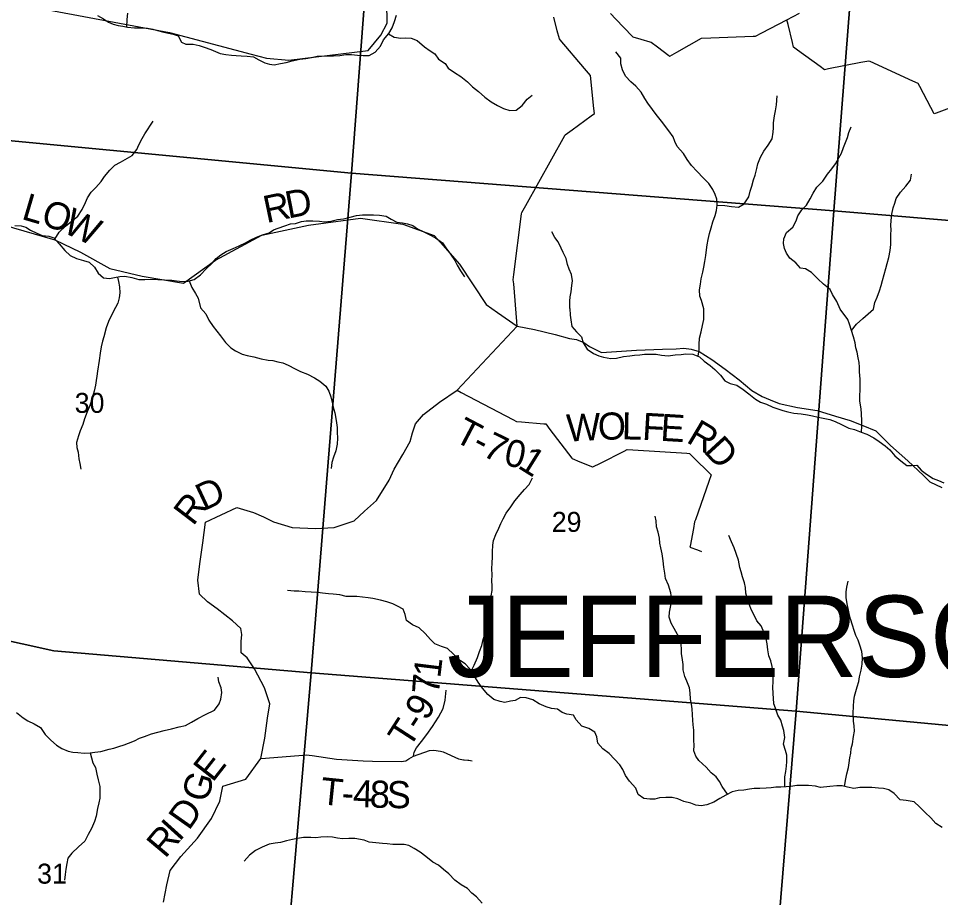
# Model space of a CAD drawing. Extents: x 1715311 to 2083412, y 146837 to 553079.
# Drawn here: x 1917955 to 1928164, y 312214 to 321945 of the extents above; entities that cross this region are included whole.
import ezdxf

# ---------------------------------------------------------------- set-up
doc = ezdxf.new("R2010")
doc.units = 0
for name, color, linetype in [('GM_X_County_Road', 7, 'Continuous'), ('GM_X_County_Road_Text', 7, 'Continuous'), ('GM_X_Minor_River', 7, 'Continuous'), ('GM_X_Section', 7, 'Continuous'), ('GM_X_Section_Text', 7, 'Continuous'), ('GM_X_State_Route', 7, 'Continuous'), ('GM_X_Township_Road', 7, 'Continuous'), ('GM_X_Township_Road_Text', 7, 'Continuous'), ('GM_X_Township_Text', 7, 'Continuous')]:
    doc.layers.add(name, color=color, linetype=linetype)

msp = doc.modelspace()

# ---------------------------------------------------------------- linework, layer by layer
at = {"layer": 'GM_X_County_Road'}
for points in [[(1924510, 321999), (1924569, 321937), (1924749, 321749), (1924758, 321740), (1924846, 321716), (1924946, 321688), (1924961, 321684), (1925032, 321631), (1925156, 321536), (1925167, 321528), (1925246, 321572), (1925518, 321725), (1925519, 321726), (1925622, 321730), (1926091, 321749), (1926117, 321750), (1926186, 321786), (1926463, 321930), (1926602, 322003)], [(1923476, 318540), (1923472, 318592), (1923438, 319007), (1923434, 319052), (1923441, 319111), (1923526, 319782), (1923528, 319797), (1923572, 319875), (1924003, 320649), (1924008, 320657), (1924084, 320713), (1924295, 320866), (1924334, 320894), (1924327, 320950), (1924288, 321312), (1924288, 321315), (1924222, 321392), (1923952, 321710), (1923944, 321720), (1923921, 321808), (1923883, 321960)], [(1916337, 320578), (1916337, 320577), (1916816, 320281), (1917394, 319907), (1917761, 319670), (1917901, 319629), (1918358, 319494), (1918643, 319358), (1918967, 319178), (1919324, 319092), (1919781, 319014), (1920137, 319268), (1920649, 319545), (1921165, 319656), (1921742, 319733), (1922209, 319667), (1922557, 319541), (1922629, 319465), (1922838, 319226), (1923134, 318780), (1923259, 318692), (1923476, 318540)], [(1919562, 312162), (1919597, 312354), (1919634, 312514), (1919751, 312668), (1919936, 312873), (1920092, 313088), (1920183, 313280), (1920216, 313446), (1920472, 313524), (1920639, 313753), (1920683, 313977), (1920713, 314199), (1920740, 314357), (1920679, 314536), (1920569, 314747), (1920486, 314868), (1920422, 314922), (1920421, 315048), (1920428, 315126), (1920418, 315191), (1920325, 315279), (1920156, 315409), (1920047, 315487), (1919961, 315574), (1919940, 315726), (1919962, 315908), (1919995, 316140), (1920027, 316369), (1920374, 316531), (1920557, 316477), (1920667, 316429), (1920778, 316374), (1920984, 316312), (1921243, 316299), (1921451, 316309), (1921673, 316384), (1921788, 316491), (1921921, 316609), (1922060, 316834), (1922113, 316956), (1922212, 317118), (1922293, 317261), (1922318, 317357), (1922352, 317459), (1922439, 317561), (1922618, 317696), (1922814, 317829), (1923476, 318540)], [(1923476, 318540), (1923667, 318502), (1923897, 318447), (1924055, 318403), (1924133, 318393), (1924213, 318359), (1924277, 318313), (1924411, 318249), (1924797, 318275), (1925085, 318286), (1925237, 318288), (1925323, 318296), (1925403, 318286), (1925493, 318258), (1925633, 318170), (1925779, 318064), (1925935, 317945), (1926074, 317825), (1926190, 317761), (1926276, 317723), (1926376, 317682), (1926582, 317638), (1926798, 317606), (1927002, 317544), (1927162, 317496), (1927302, 317439), (1927446, 317379), (1927610, 317217), (1927802, 317048), (1927977, 316886), (1928047, 316816), (1928177, 316754)]]:
    msp.add_lwpolyline(points, dxfattribs=at)
at = {"layer": 'GM_X_Minor_River'}
for points in [[(1919155, 321850), (1919160, 321932), (1919167, 322005)], [(1918829, 321976), (1918897, 321941), (1918952, 321905), (1919004, 321883), (1919058, 321867), (1919110, 321859), (1919164, 321848), (1919240, 321842), (1919314, 321840), (1919384, 321838), (1919443, 321827), (1919495, 321811), (1919563, 321795), (1919617, 321783), (1919669, 321770), (1919723, 321752), (1919759, 321684), (1919810, 321662), (1919888, 321662), (1919956, 321647), (1920010, 321627), (1920084, 321603), (1920136, 321579), (1920188, 321558), (1920251, 321546), (1920315, 321538), (1920367, 321534), (1920419, 321531), (1920489, 321529), (1920557, 321519), (1920615, 321487), (1920682, 321452), (1920736, 321438), (1920788, 321432), (1920856, 321446), (1920918, 321458), (1920984, 321475)], [(1920984, 321475), (1921070, 321495), (1921138, 321503), (1921200, 321513), (1921264, 321526), (1921368, 321530), (1921444, 321532), (1921514, 321535), (1921580, 321545), (1921644, 321547), (1921710, 321539), (1921771, 321536), (1921837, 321534), (1921905, 321570), (1921962, 321638), (1921996, 321710), (1922054, 321779), (1922092, 321843), (1922120, 321913), (1922141, 321981)], [(1922051, 321776), (1922114, 321739), (1922188, 321727), (1922244, 321731), (1922303, 321728), (1922371, 321700), (1922451, 321630), (1922515, 321586), (1922566, 321553), (1922606, 321493), (1922678, 321447), (1922712, 321395), (1922781, 321346), (1922853, 321302), (1922925, 321244), (1922983, 321189), (1923048, 321137), (1923120, 321075), (1923188, 321023), (1923257, 320980), (1923325, 320948), (1923395, 320926), (1923467, 320931), (1923531, 320983), (1923589, 321051), (1923641, 321097)], [(1925544, 318731), (1925517, 318822), (1925499, 318872), (1925497, 318940), (1925505, 319002), (1925515, 319062), (1925532, 319136), (1925544, 319192), (1925554, 319254), (1925566, 319322), (1925573, 319382), (1925581, 319440), (1925591, 319500), (1925605, 319564), (1925623, 319626), (1925644, 319694), (1925670, 319764), (1925684, 319818), (1925692, 319880), (1925689, 319944), (1925667, 319998), (1925643, 320052), (1925599, 320117), (1925536, 320179), (1925470, 320251), (1925408, 320316), (1925359, 320384), (1925317, 320452), (1925247, 320526), (1925221, 320582), (1925202, 320635), (1925156, 320701), (1925076, 320809), (1925015, 320883), (1924975, 320936), (1924925, 321006), (1924890, 321060), (1924848, 321130), (1924790, 321195), (1924735, 321245), (1924677, 321307), (1924643, 321375), (1924625, 321443), (1924626, 321507), (1924570, 321576)], [(1925692, 319880), (1925776, 319874), (1925848, 319862), (1925926, 319855), (1925988, 319893), (1926040, 319969), (1926058, 320035), (1926075, 320087), (1926093, 320157), (1926111, 320209), (1926131, 320283), (1926141, 320335), (1926170, 320409), (1926208, 320477), (1926256, 320544), (1926298, 320614), (1926312, 320686), (1926313, 320736), (1926315, 320788), (1926327, 320868), (1926337, 320922), (1926346, 320990), (1926354, 321090)], [(1918357, 319503), (1918407, 319580), (1918475, 319645), (1918535, 319695), (1918613, 319757), (1918661, 319831), (1918697, 319909), (1918720, 319961), (1918760, 320023), (1918812, 320072), (1918870, 320140), (1918908, 320194), (1918966, 320266), (1919022, 320320), (1919085, 320356), (1919161, 320397), (1919215, 320427), (1919267, 320493), (1919287, 320545), (1919325, 320617), (1919355, 320669), (1919448, 320809)], [(1927054, 318728), (1927017, 318812), (1926969, 318889), (1926943, 318945), (1926868, 319005), (1926804, 319061), (1926736, 319134), (1926668, 319174), (1926614, 319182), (1926563, 319240), (1926497, 319293), (1926459, 319347), (1926436, 319397), (1926424, 319455), (1926428, 319505), (1926460, 319575), (1926528, 319633), (1926566, 319703), (1926585, 319759), (1926627, 319827), (1926679, 319878), (1926719, 319948), (1926753, 320010), (1926796, 320076), (1926860, 320144), (1926914, 320220), (1926962, 320280), (1927002, 320335), (1927038, 320401), (1927069, 320455), (1927091, 320515), (1927111, 320573), (1927133, 320629), (1927149, 320681), (1927176, 320747)], [(1927420, 318727), (1927438, 318801), (1927462, 318861), (1927488, 318929), (1927507, 318989), (1927523, 319043), (1927539, 319111), (1927557, 319177), (1927573, 319234), (1927592, 319300), (1927606, 319378), (1927612, 319443), (1927614, 319505), (1927615, 319555), (1927617, 319605), (1927615, 319655), (1927619, 319709), (1927625, 319779), (1927640, 319847), (1927658, 319899), (1927674, 319951), (1927722, 320022), (1927780, 320088), (1927831, 320156), (1927841, 320222)], [(1920145, 319287), (1920197, 319327), (1920253, 319367), (1920331, 319400), (1920399, 319428), (1920467, 319462), (1920521, 319492), (1920589, 319525), (1920657, 319549), (1920729, 319571), (1920780, 319607), (1920832, 319623), (1920906, 319650), (1920968, 319670), (1921023, 319676), (1921089, 319698), (1921141, 319705), (1921213, 319703), (1921289, 319701), (1921343, 319693), (1921415, 319702), (1921489, 319720), (1921555, 319728), (1921629, 319746), (1921697, 319765), (1921763, 319771), (1921829, 319773), (1921887, 319771), (1921953, 319766), (1922025, 319758), (1922082, 319724), (1922146, 319690), (1922206, 319683), (1922264, 319671), (1922320, 319653), (1922374, 319617), (1922443, 319582), (1922509, 319550), (1922573, 319516), (1922649, 319460), (1922686, 319405), (1922738, 319335), (1922786, 319265), (1922813, 319215), (1922851, 319151), (1922895, 319086)], [(1917915, 319652), (1917985, 319649), (1918037, 319633), (1918089, 319603), (1918159, 319567), (1918219, 319544), (1918292, 319534), (1918346, 319516), (1918404, 319450), (1918470, 319375), (1918527, 319321), (1918597, 319287), (1918675, 319266), (1918739, 319248), (1918797, 319192), (1918836, 319124), (1918898, 319073), (1918964, 319067), (1919020, 319077), (1919078, 319087), (1919134, 319093), (1919210, 319078), (1919287, 319056), (1919353, 319054), (1919427, 319059), (1919499, 319055), (1919573, 319051), (1919653, 319047), (1919705, 319042), (1919773, 319034), (1919833, 319036), (1919901, 319056), (1919969, 319107), (1920035, 319173), (1920101, 319235), (1920145, 319287)], [(1924060, 318734), (1924058, 318814), (1924065, 318864), (1924073, 318920), (1924081, 318990), (1924089, 319042), (1924077, 319112), (1924052, 319168), (1924034, 319222), (1924020, 319288), (1923986, 319354), (1923965, 319404), (1923929, 319471), (1923895, 319521), (1923862, 319583)], [(1919051, 319082), (1919064, 319033), (1919075, 318975), (1919079, 318909), (1919069, 318851), (1919055, 318793), (1919030, 318745)], [(1919846, 319040), (1919876, 318968), (1919916, 318900), (1919946, 318849), (1919969, 318743)], [(1919030, 318745), (1918977, 318645), (1918951, 318591), (1918925, 318521), (1918900, 318421), (1918886, 318371), (1918872, 318311), (1918858, 318239), (1918848, 318157), (1918831, 318041), (1918823, 317987), (1918817, 317937), (1918809, 317885), (1918795, 317821), (1918778, 317767), (1918762, 317715), (1918740, 317651), (1918714, 317591), (1918686, 317513), (1918666, 317451), (1918637, 317381), (1918619, 317325), (1918599, 317253), (1918603, 317194), (1918615, 317144), (1918624, 317070), (1918634, 317020), (1918646, 316956)], [(1919969, 318743), (1920028, 318674), (1920062, 318606), (1920110, 318536), (1920150, 318483), (1920191, 318431), (1920249, 318359), (1920305, 318299), (1920359, 318267), (1920433, 318230), (1920489, 318214), (1920561, 318198), (1920642, 318176), (1920718, 318161), (1920770, 318157), (1920826, 318145), (1920882, 318133), (1920942, 318109), (1921018, 318068), (1921078, 318038), (1921155, 318008), (1921231, 317968), (1921293, 317929), (1921357, 317875), (1921391, 317819), (1921413, 317757), (1921432, 317679), (1921444, 317629), (1921458, 317579), (1921468, 317518), (1921476, 317468), (1921483, 317416), (1921485, 317366), (1921489, 317300), (1921483, 317234), (1921469, 317160), (1921442, 317090), (1921424, 317028), (1921416, 316962)], [(1924060, 318734), (1924065, 318660), (1924071, 318608), (1924083, 318536), (1924133, 318478), (1924189, 318419), (1924206, 318353), (1924252, 318285), (1924320, 318237), (1924380, 318209), (1924434, 318196), (1924512, 318182), (1924578, 318186), (1924654, 318204), (1924724, 318211), (1924776, 318217), (1924834, 318223), (1924887, 318229), (1925017, 318229), (1925075, 318218), (1925149, 318210), (1925227, 318220), (1925293, 318226), (1925345, 318232), (1925421, 318229), (1925495, 318201), (1925547, 318153), (1925613, 318105), (1925666, 318060), (1925728, 317998), (1925774, 317934), (1925836, 317904), (1925910, 317886), (1925978, 317839), (1926043, 317791), (1926115, 317729), (1926169, 317697), (1926237, 317674), (1926307, 317644), (1926361, 317624), (1926418, 317604), (1926474, 317590), (1926540, 317577), (1926620, 317567), (1926692, 317559), (1926746, 317545), (1926808, 317532), (1926864, 317520), (1926938, 317504), (1926996, 317484), (1927068, 317452), (1927149, 317411), (1927213, 317395), (1927285, 317367), (1927349, 317343), (1927425, 317304), (1927485, 317264), (1927550, 317216), (1927604, 317170), (1927658, 317103), (1927726, 317049), (1927790, 316995), (1927844, 316995), (1927902, 317001), (1927951, 316944), (1928007, 316900), (1928081, 316854), (1928141, 316830), (1928201, 316803)], [(1925480, 318207), (1925493, 318281), (1925491, 318335), (1925496, 318405), (1925512, 318477), (1925530, 318547), (1925544, 318611), (1925544, 318731)], [(1927288, 317366), (1927293, 317431), (1927293, 317491), (1927288, 317567), (1927284, 317623), (1927270, 317707), (1927270, 317769), (1927275, 317833), (1927273, 317893), (1927273, 317954), (1927267, 318032), (1927265, 318086), (1927262, 318136), (1927252, 318188), (1927240, 318250), (1927226, 318300), (1927218, 318356), (1927200, 318422), (1927179, 318492), (1927157, 318561), (1927137, 318613), (1927054, 318728)], [(1927179, 318492), (1927235, 318562), (1927303, 318622), (1927420, 318727)], [(1922967, 314721), (1923002, 314785), (1923038, 314873), (1923061, 314937), (1923085, 315005), (1923099, 315071), (1923117, 315125), (1923129, 315193), (1923148, 315255), (1923162, 315321), (1923180, 315393), (1923190, 315471), (1923190, 315555), (1923199, 315613), (1923199, 315665), (1923197, 315721), (1923199, 315785), (1923197, 315853), (1923200, 315919), (1923202, 315983), (1923202, 316042), (1923206, 316116), (1923216, 316168), (1923240, 316232), (1923273, 316302), (1923295, 316354), (1923321, 316406), (1923355, 316468), (1923405, 316538), (1923451, 316607), (1923508, 316677), (1923556, 316731), (1923608, 316785), (1923646, 316859)], [(1925806, 313357), (1925746, 313445), (1925718, 313499), (1925680, 313549), (1925625, 313595), (1925569, 313658), (1925489, 313730), (1925453, 313780), (1925433, 313838), (1925436, 313900), (1925434, 313952), (1925434, 314013), (1925432, 314067), (1925424, 314125), (1925423, 314179), (1925419, 314235), (1925413, 314303), (1925407, 314355), (1925397, 314411), (1925392, 314479), (1925386, 314537), (1925356, 314609), (1925332, 314662), (1925316, 314734), (1925315, 314794), (1925307, 314846), (1925295, 314916), (1925295, 314966), (1925289, 315054), (1925250, 315126), (1925214, 315191), (1925180, 315251), (1925160, 315317), (1925162, 315373), (1925179, 315447), (1925187, 315529), (1925179, 315587), (1925151, 315673), (1925118, 315747), (1925110, 315806), (1925102, 315872), (1925094, 315940), (1925082, 316018), (1925067, 316086), (1925057, 316138), (1925051, 316192), (1925037, 316260), (1925021, 316318), (1925014, 316385), (1925004, 316435)], [(1926439, 313440), (1926440, 313549), (1926450, 313609), (1926458, 313669), (1926464, 313721), (1926463, 313791), (1926449, 313841), (1926425, 313913), (1926441, 313987), (1926429, 314062), (1926416, 314112), (1926394, 314176), (1926364, 314234), (1926338, 314310), (1926320, 314360), (1926313, 314420), (1926311, 314470), (1926309, 314547), (1926311, 314599), (1926311, 314653), (1926310, 314703), (1926300, 314773), (1926284, 314835), (1926264, 314889), (1926252, 314957), (1926243, 315023), (1926233, 315079), (1926213, 315145), (1926179, 315220), (1926131, 315278), (1926102, 315340), (1926070, 315396), (1926044, 315462), (1926026, 315516), (1926010, 315585), (1926003, 315645), (1925993, 315697), (1925971, 315765), (1925955, 315819), (1925943, 315869), (1925926, 315947), (1925878, 316084), (1925848, 316152), (1925821, 316222)], [(1927100, 313445), (1927115, 313527), (1927127, 313583), (1927146, 313655), (1927152, 313705), (1927160, 313761), (1927170, 313813), (1927176, 313863), (1927188, 313917), (1927201, 313995), (1927211, 314057), (1927209, 314115), (1927201, 314165), (1927197, 314250), (1927202, 314332), (1927204, 314392), (1927212, 314444), (1927226, 314494), (1927242, 314548), (1927259, 314604), (1927267, 314656), (1927285, 314730), (1927297, 314798), (1927301, 314866), (1927294, 314938), (1927272, 315008), (1927252, 315064), (1927228, 315116), (1927208, 315171), (1927189, 315229), (1927167, 315299), (1927153, 315357), (1927141, 315413), (1927129, 315465), (1927118, 315535), (1927120, 315597), (1927126, 315651), (1927140, 315717)], [(1924946, 313305), (1924878, 313309), (1924818, 313356), (1924789, 313426), (1924721, 313502), (1924677, 313564), (1924645, 313632), (1924614, 313683), (1924556, 313747), (1924496, 313809), (1924424, 313859), (1924371, 313924), (1924357, 313992), (1924337, 314046), (1924269, 314084), (1924193, 314112), (1924131, 314183), (1924100, 314233), (1924026, 314243), (1923974, 314263), (1923922, 314301), (1923856, 314306), (1923798, 314326), (1923720, 314360), (1923649, 314404), (1923577, 314423), (1923513, 314429), (1923455, 314395), (1923403, 314387), (1923339, 314375), (1923287, 314385), (1923217, 314408), (1923151, 314462), (1923091, 314532), (1923044, 314600), (1922996, 314675), (1922950, 314749), (1922902, 314801), (1922848, 314833), (1922771, 314910), (1922707, 314972), (1922637, 314994), (1922565, 315022), (1922517, 315072), (1922458, 315137), (1922390, 315201), (1922318, 315233), (1922252, 315280), (1922238, 315346), (1922215, 315408), (1922153, 315440), (1922101, 315466), (1922033, 315486), (1921965, 315505), (1921879, 315525), (1921827, 315531), (1921765, 315539), (1921701, 315545), (1921646, 315548), (1921582, 315548), (1921512, 315566), (1921438, 315572), (1921386, 315576), (1921322, 315583), (1921270, 315591), (1921196, 315595), (1921130, 315597), (1921060, 315605), (1921006, 315606), (1920934, 315612)], [(1919174, 313923), (1919240, 313949), (1919294, 313977), (1919350, 313997), (1919428, 314026), (1919500, 314046), (1919570, 314062), (1919648, 314082), (1919734, 314102), (1919804, 314117), (1919870, 314155), (1919941, 314197), (1920025, 314241), (1920125, 314289), (1920177, 314359), (1920195, 314411), (1920205, 314485), (1920199, 314537), (1920174, 314603), (1920168, 314655)], [(1917934, 314261), (1918006, 314205), (1918058, 314171), (1918128, 314138), (1918198, 314096), (1918249, 314018), (1918313, 313956), (1918377, 313901), (1918435, 313865), (1918506, 313835), (1918558, 313825), (1918614, 313821), (1918682, 313814), (1918748, 313816), (1918800, 313824), (1918868, 313832), (1918958, 313856), (1919010, 313869), (1919068, 313887), (1919124, 313905), (1919174, 313923)], [(1918750, 313816), (1918780, 313704), (1918808, 313654), (1918823, 313580), (1918837, 313516), (1918855, 313445), (1918857, 313383), (1918857, 313313), (1918846, 313261), (1918832, 313199), (1918816, 313115), (1918796, 313055), (1918762, 312977), (1918727, 312911), (1918689, 312839), (1918619, 312777), (1918547, 312707), (1918503, 312651), (1918491, 312591), (1918480, 312527), (1918472, 312469), (1918466, 312407)], [(1928181, 312989), (1928111, 313035), (1928057, 313098), (1927992, 313154), (1927930, 313218), (1927872, 313274), (1927782, 313289), (1927716, 313297), (1927652, 313367), (1927593, 313407), (1927533, 313422), (1927477, 313426), (1927405, 313434), (1927271, 313434), (1927203, 313423), (1927135, 313437), (1927073, 313451), (1927017, 313451), (1926939, 313443), (1926835, 313432), (1926779, 313446), (1926703, 313454), (1926627, 313454), (1926573, 313454), (1926507, 313445), (1926454, 313441), (1926394, 313437), (1926342, 313437), (1926288, 313429), (1926234, 313425), (1926162, 313422), (1926102, 313422), (1926050, 313414), (1925986, 313402), (1925922, 313398), (1925856, 313385), (1925788, 313347), (1925722, 313309), (1925654, 313269), (1925578, 313241), (1925512, 313229), (1925456, 313238), (1925400, 313258), (1925322, 313276), (1925254, 313308), (1925194, 313322), (1925122, 313321), (1925054, 313317), (1925002, 313305), (1924946, 313305)], [(1923090, 312153), (1923028, 312222), (1922976, 312262), (1922925, 312314), (1922855, 312356), (1922787, 312405), (1922721, 312475), (1922661, 312525), (1922604, 312573), (1922542, 312606), (1922466, 312670), (1922402, 312718), (1922336, 312758), (1922278, 312789), (1922227, 312801), (1922155, 312803), (1922101, 312801), (1922039, 312809), (1921987, 312811), (1921913, 312820), (1921837, 312828), (1921781, 312850), (1921681, 312866), (1921613, 312867), (1921541, 312863), (1921489, 312871), (1921433, 312883), (1921373, 312885), (1921303, 312882), (1921246, 312876), (1921192, 312878), (1921112, 312880), (1921046, 312868), (1920988, 312856), (1920922, 312841), (1920858, 312823), (1920798, 312817), (1920732, 312805), (1920652, 312773), (1920580, 312734), (1920513, 312682), (1920455, 312618)]]:
    msp.add_lwpolyline(points, dxfattribs=at)
at = {"layer": 'GM_X_Section'}
for points in [[(1916671, 326031), (1922052, 325629), (1921641, 320234), (1916286, 320743)], [(1922052, 325629), (1927402, 325216), (1926983, 319817), (1921641, 320234)], [(1927402, 325216), (1932682, 324783), (1932199, 319380), (1926983, 319817)], [(1921641, 320234), (1921197, 314700), (1918345, 314946), (1915890, 315487), (1916286, 320743)], [(1926983, 319817), (1926567, 314279), (1921197, 314700), (1921641, 320234)], [(1932199, 319380), (1931734, 313795), (1926567, 314279), (1926983, 319817)], [(1915890, 315487), (1918345, 314946), (1921197, 314700), (1920763, 309706), (1920291, 309730), (1915475, 310092)], [(1921197, 314700), (1926567, 314279), (1926152, 309257), (1925779, 309287), (1920763, 309706)], [(1926567, 314279), (1931734, 313795), (1931307, 308842), (1930934, 308872), (1926152, 309257)]]:
    msp.add_lwpolyline(points, close=True, dxfattribs=at)
at = {"layer": 'GM_X_State_Route'}
msp.add_lwpolyline([(1918068, 322080), (1919628, 321789), (1920532, 321549), (1920700, 321505), (1920948, 321485), (1921826, 321591), (1921968, 321759), (1922037, 321892), (1922022, 322822)], dxfattribs=at)
at = {"layer": 'GM_X_Township_Road'}
for points in [[(1928700, 321116), (1928115, 320896), (1928093, 320888), (1928056, 320959), (1927935, 321190), (1927917, 321225), (1927858, 321251), (1927384, 321467), (1927371, 321473), (1927282, 321456), (1926925, 321386), (1926881, 321377), (1926832, 321412), (1926579, 321595), (1926537, 321626), (1926525, 321677), (1926476, 321879), (1926463, 321930)], [(1922814, 317829), (1922858, 317806), (1923430, 317505), (1923470, 317484), (1923524, 317479), (1923771, 317458), (1923794, 317456), (1923840, 317395), (1924080, 317078), (1924084, 317073), (1924170, 317038), (1924309, 316983), (1924316, 316980), (1924398, 317022), (1924663, 317157), (1924694, 317173), (1924759, 317169), (1925354, 317133), (1925385, 317131), (1925433, 317083), (1925609, 316907), (1925623, 316892), (1925597, 316818), (1925450, 316396), (1925441, 316373), (1925428, 316299), (1925391, 316104), (1925389, 316094), (1925473, 316062), (1925519, 316044)], [(1922328, 313778), (1922336, 313825), (1922361, 313870), (1922419, 313940), (1922475, 314019), (1922541, 314107), (1922606, 314212), (1922658, 314305), (1922679, 314399), (1922689, 314509)], [(1920639, 313753), (1920690, 313758), (1921103, 313792), (1921140, 313795), (1921206, 313788), (1921476, 313745), (1921772, 313727), (1921772, 313727), (1921875, 313723), (1922193, 313719), (1922245, 313729), (1922279, 313750), (1922328, 313778), (1922506, 313841), (1922553, 313846), (1922627, 313833), (1922657, 313826), (1922828, 313748), (1922883, 313737), (1922888, 313737), (1922932, 313735), (1922940, 313735), (1922980, 313729)]]:
    msp.add_lwpolyline(points, dxfattribs=at)

# ---------------------------------------------------------------- texts
at = {"layer": 'GM_X_County_Road_Text'}
for s, rotation, p in [('D', 11.0849, (1920941, 319729)), ('L', 343.5805, (1917978, 319728)), ('R', 11.8519, (1920701, 319679)), ('O', 341.6065, (1918190, 319666)), ('W', 334.478, (1918432, 319586)), ('D', 25.1802, (1920009, 316490)), ('R', 52.6422, (1919889, 316318)), ('E', 51.9352, (1920105, 313480)), ('G', 72.5853, (1920039, 313253)), ('D', 54.8392, (1919842, 312947)), ('I', 47.982, (1919735, 312825)), ('R', 50.0015, (1919579, 312638))]:
    msp.add_text(s, height=300, rotation=rotation, dxfattribs=at).set_placement(p)
at = {"layer": 'GM_X_Section_Text'}
for s, p in [('30', (1918578, 317579)), ('29', (1923860, 316262)), ('31', (1918162, 312368))]:
    msp.add_text(s, height=221, rotation=0, dxfattribs=at).set_placement(p)
at = {"layer": 'GM_X_Township_Road_Text'}
for s, rotation, p in [('T', 332.2788, (1922762, 317276)), ('W', 2.6735, (1924028, 317261)), ('O', 1.8837, (1924374, 317278)), ('L', 358.9671, (1924634, 317286)), ('F', 356.7198, (1924856, 317282)), ('E', 356.4793, (1925057, 317271)), ('R', 329.3261, (1925338, 317261)), ('7', 333.9429, (1923077, 317111)), ('D', 312.5548, (1925532, 317150)), ('-', 332.5238, (1922961, 317171)), ('0', 348.0657, (1923318, 317005)), ('1', 328.002, (1923471, 316977)), ('1', 82.9451, (1922624, 314637)), ('7', 85.8891, (1922611, 314458)), ('9', 60.1971, (1922477, 314160)), ('T', 57.1439, (1922281, 313854)), ('-', 57.3359, (1922403, 314043)), ('T', 354.2003, (1921288, 313249)), ('4', 357.8566, (1921655, 313219)), ('8', 357.935, (1921840, 313212)), ('S', 358.8721, (1922030, 313206)), ('-', 357.536, (1921530, 313225))]:
    msp.add_text(s, height=300, rotation=rotation, dxfattribs=at).set_placement(p)
at = {"layer": 'GM_X_Township_Text'}
msp.add_text('JEFFERSON', height=900, rotation=0, dxfattribs=at).set_placement((1922701, 314656))

doc.saveas('drawing.dxf')
